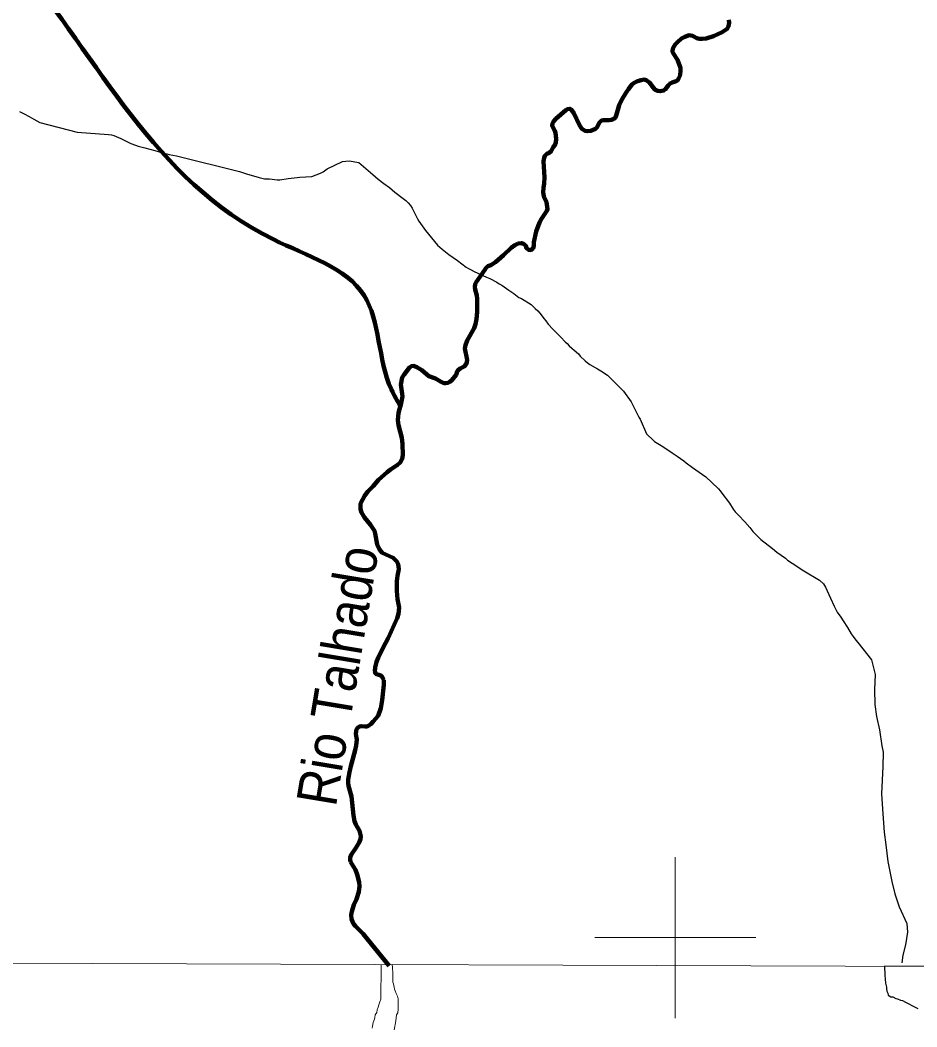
# Model space of a CAD drawing. Extents: x 553962 to 842807, y 8883888 to 9032388.
# Drawn here: x 616862 to 628002, y 8948891 to 8961392 of the extents above; entities that cross this region are included whole.
import ezdxf
from ezdxf.enums import TextEntityAlignment as Align

# ---------------------------------------------------------------- set-up
doc = ezdxf.new("R2010")
doc.units = 0
doc.header["$LTSCALE"] = 200
for name, color, linetype, lineweight in [('1', 7, 'Continuous', 13), ('12', 7, 'Continuous', 25), ('2', 7, 'Continuous', 13), ('21', 7, 'Continuous', 25), ('24', 7, 'Continuous', 25), ('25', 7, 'Continuous', 13), ('9', 7, 'Continuous', 90)]:
    doc.layers.add(name, color=color, linetype=linetype, lineweight=lineweight)
doc.layers.add('49', color=7, linetype='Continuous')

msp = doc.modelspace()

# ---------------------------------------------------------------- linework, layer by layer
at = {"layer": '1'}
msp.add_line((565315.3, 8949866.8), (791497.7, 8949052.2), dxfattribs=at)
at = {"layer": '12'}
for points in [[(616854.8, 8960258.8), (616911.9, 8960228.8), (616972.5, 8960193.8), (617033, 8960160.9), (617107.9, 8960123.1)], [(617107.9, 8960123.1), (617571.3, 8960000.1), (617961.2, 8959971.1), (617997, 8959967.1), (618026, 8959959.2), (618054, 8959949.2), (618114.7, 8959924.2), (618235.7, 8959862.3), (618293.7, 8959838.4), (618327.5, 8959827.4), (618413, 8959804.5), (618473.5, 8959791.6), (618533.2, 8959772.7), (618617.9, 8959748.8), (618652.5, 8959740.8), (618682.4, 8959731.8), (618711.4, 8959723.9), (618803.6, 8959709), (619586.3, 8959511.3)], [(619831.3, 8959436.2), (619865.1, 8959428.2), (619897.1, 8959423.3), (619929, 8959423.3), (619960.1, 8959421.4), (620056, 8959410.5), (620088, 8959410.6), (620193.3, 8959426.8), (620302, 8959438.9), (620338.3, 8959444), (620485.1, 8959452.2), (620592.3, 8959491.5), (620626.6, 8959508.6), (620677.1, 8959543.7), (620866.8, 8959636.1), (620950.1, 8959645.3), (621067.6, 8959622.4), (621213.8, 8959498.5), (621277.5, 8959446.5), (621310.7, 8959416.5), (621378.9, 8959364.5), (621451.2, 8959312.6), (621517.4, 8959257.6), (621620.6, 8959177.6), (621652, 8959151.6), (621681.1, 8959122.6), (621709.4, 8959090.6), (621730.8, 8959055.6), (621766, 8958989.6), (621797.6, 8958926.5), (621816.7, 8958894.5), (621897.9, 8958779.4), (622047.1, 8958598.4), (622104.4, 8958547.4), (622189, 8958482.4), (622295.2, 8958408.5), (622402.8, 8958323.5), (622432, 8958306.5), (622464.2, 8958290.6), (622503.3, 8958272.6), (622656.9, 8958198.7), (622695.9, 8958184.8), (622781.7, 8958137.8), (622814.5, 8958116.8), (622845, 8958100.9), (622933, 8958040.9), (622994, 8957997), (623055.6, 8957949), (623090.1, 8957935), (623208.6, 8957861.1), (623261.3, 8957811.1), (623293.1, 8957783.1), (623319, 8957753.1), (623370.1, 8957684.1), (623394.1, 8957657.1), (623423, 8957618), (623480.8, 8957556), (623503.5, 8957528), (623577.3, 8957455), (623634.3, 8957397), (623656.2, 8957377), (623681.5, 8957349), (623715.2, 8957318), (623746.4, 8957294), (623796.4, 8957250.1), (623820, 8957220), (623881.1, 8957162.1), (623907.7, 8957139.1), (623938.3, 8957116.1), (624032.6, 8957060.1), (624097.3, 8957025.2), (624126.4, 8957005.2), (624156.6, 8956982.2), (624209.6, 8956933.2), (624300.1, 8956843.2), (624356.6, 8956783.2), (624452.3, 8956653.2), (624547.5, 8956464), (624563.3, 8956437), (624643.8, 8956253.8), (624732.1, 8956169.8), (624741.4, 8956157.8), (624844.8, 8956096.9), (624963, 8956021), (625024.6, 8955976), (625106.9, 8955919.1), (625134.8, 8955896.1), (625215.8, 8955838.1), (625381.6, 8955722.2), (625453.3, 8955650.2), (625539.4, 8955570.2), (625559, 8955549.2), (625578.1, 8955517.2), (625672.3, 8955394.1), (625719.6, 8955321.1), (625744.1, 8955288.1), (625787.2, 8955246.1), (625865, 8955162.1), (625928.3, 8955090.1), (625962.8, 8955044), (626062.5, 8954941)], [(619586.3, 8959511.3), (619636.3, 8959496), (619674.1, 8959485), (619831.3, 8959436.2)], [(626062.5, 8954941), (626210.1, 8954830.1), (626263.6, 8954786.1), (626369.3, 8954710.2), (626395.7, 8954688.2), (626508.6, 8954610.2), (626539.2, 8954592.2), (626598.2, 8954554.3), (626792.1, 8954439.4), (626840.8, 8954390.4), (626864.8, 8954350.4), (626929.5, 8954214.3), (626976, 8954113.2), (627012.7, 8954042.1), (627056.3, 8953977.1), (627085.1, 8953931.1), (627140.4, 8953852), (627187.4, 8953773), (627209.8, 8953740), (627243.8, 8953694), (627268.1, 8953665), (627437.5, 8953449.9)], [(627437.5, 8953449.9), (627481.8, 8953267.7), (627474.2, 8953079.4), (627481, 8952894.1), (627502, 8952745.9), (627539.5, 8952577.7), (627565.1, 8952382.4), (627583.5, 8952301.3), (627578.9, 8952122), (627564.2, 8951783.5), (627578, 8951538.1), (627594.5, 8951309.8), (627615.6, 8951152.6), (627641.3, 8950944.3), (627690, 8950694), (627726.6, 8950540.8), (627780.8, 8950380.6), (627876.2, 8950172.5), (627886.3, 8950067.3), (627860.6, 8949911), (627825.7, 8949779.8), (627813.3, 8949686.6)]]:
    msp.add_lwpolyline(points, dxfattribs=at)
at = {"layer": '2'}
for p, q in [((625000, 8949000), (625000, 8951000)), ((624000, 8950000), (626000, 8950000))]:
    msp.add_line(p, q, dxfattribs=at)
at = {"layer": '21'}
msp.add_lwpolyline([(628960.2, 8949636.4), (627600.1, 8949642.9), (627603.7, 8949532.3), (627605.9, 8949482.3), (627610.5, 8949432.2), (627625.2, 8949384.6), (627625.1, 8949364.6), (627627.4, 8949332), (627639.7, 8949309.5), (627644.5, 8949284.4), (627676.9, 8949264.2), (627704.4, 8949261.6), (627739.3, 8949243.9), (627761.7, 8949238.7), (627796.6, 8949223.5), (627824.1, 8949218.4), (627859, 8949198.2), (627903.8, 8949177.9), (627948.7, 8949152.7), (628014.1, 8949120.8)], dxfattribs=at)
at = {"layer": '24'}
for points in [[(625664.5, 8961397.5), (625669.9, 8961359.4), (625663.1, 8961316.3), (625644, 8961283.3), (625582.5, 8961243.1), (625473.5, 8961191.8)], [(625473.5, 8961191.8), (625385.3, 8961162.7), (625335.4, 8961158.6), (625297, 8961160.5), (625268.2, 8961168.5), (625214.1, 8961198.5), (625173.4, 8961205.4), (625117.9, 8961186.3), (625078.9, 8961163.2), (625027.5, 8961119), (625000.9, 8961089), (624975.3, 8961048.8), (624966.1, 8961016.8), (624966.2, 8960999.8), (624973, 8960982.7), (625029.9, 8960900.7), (625064.6, 8960798.6), (625067, 8960768.6), (625061.1, 8960709.5), (625046, 8960671.4), (625027.5, 8960644.3), (625011.3, 8960634.2), (624961, 8960619.2), (624936.3, 8960606.1), (624912, 8960582), (624879.5, 8960536.9), (624854.3, 8960516.8), (624811.3, 8960509.7), (624784.5, 8960512.7), (624750.7, 8960527.7), (624725.6, 8960556.7), (624680, 8960618.7), (624640.1, 8960648.7), (624615.7, 8960653.7), (624577.3, 8960648.6), (624531.2, 8960635.5), (624496.8, 8960619.4)], [(624496.8, 8960619.4), (624466.5, 8960595.3), (624466.5, 8960595.3), (624418.2, 8960536.2), (624388.4, 8960493.1), (624334.1, 8960398.8), (624304.9, 8960334.7), (624271.6, 8960219.4), (624255.9, 8960184.4), (624237, 8960167.3), (624209.4, 8960152.2), (624177.8, 8960149.2), (624105.6, 8960150.1), (624084, 8960144), (624056.4, 8960117.9), (624029.7, 8960062.8), (624008.5, 8960040.7), (623952.6, 8960017.6), (623906.6, 8960011.5), (623879.7, 8960018.5), (623839.9, 8960041.5), (623809.1, 8960087.5), (623742.1, 8960236.6), (623708.6, 8960280.6), (623691, 8960291.6), (623663.5, 8960287.6), (623642.3, 8960274.5), (623518.1, 8960166.2), (623487.9, 8960132.1), (623473.9, 8960107), (623469.3, 8960080), (623503, 8960016.9), (623511.8, 8959991.9), (623518.8, 8959918.8), (623515.2, 8959871.7), (623503, 8959841.6), (623483.8, 8959814.6), (623458.3, 8959764.4), (623435.3, 8959743.4), (623405.8, 8959733.3), (623380.1, 8959708.2), (623370, 8959684.2), (623363, 8959639.1), (623374, 8959437.8), (623371.3, 8959365.7), (623362.7, 8959309.6), (623359.5, 8959254.5), (623367, 8959203.4), (623399.7, 8959131.4), (623414.8, 8959045.2), (623404.2, 8959022.2), (623338.3, 8958926.9), (623315, 8958880.8), (623272.9, 8958769.6), (623243.1, 8958633.3), (623241.6, 8958590.3), (623234, 8958561.2), (623207.1, 8958537.1), (623180.9, 8958538.1), (623154, 8958559.1), (623142.4, 8958588.1), (623129.2, 8958606.1), (623114.3, 8958616.1), (623091.3, 8958624.1), (623048.1, 8958618)], [(623048.1, 8958618), (623008.6, 8958598.9), (622961, 8958563.8), (622867, 8958474.5), (622765.3, 8958385.2), (622710.3, 8958350.1), (622672.6, 8958336), (622645.8, 8958310.9), (622635.8, 8958292.8), (622526.4, 8958139.4), (622516.5, 8958114.4), (622511.7, 8958078.3), (622515.3, 8958048.3), (622533.3, 8957971.2), (622537.7, 8957930.1), (622539.2, 8957771.9), (622532.6, 8957678.7), (622519.6, 8957617.6), (622503, 8957566.5), (622414.7, 8957413.1), (622392.8, 8957358), (622387.2, 8957313.9), (622413.1, 8957173.7), (622412, 8957144.7), (622401.3, 8957121.6), (622379.3, 8957091.6), (622329.5, 8957067.4), (622303.6, 8957046.4), (622292.3, 8957028.3), (622277.2, 8956988.2), (622224.7, 8956922.1), (622199.4, 8956902), (622173.6, 8956888.9), (622144.5, 8956882.9), (622124.1, 8956884.8), (622082.2, 8956903.8), (622023.4, 8956940.8)], [(622023.4, 8956940.8), (621940, 8956970.7), (621852.9, 8957044.7), (621852.9, 8957044.7), (621788.3, 8957084.6), (621747.1, 8957098.6), (621722, 8957094.5), (621699.9, 8957079.5), (621630.5, 8956993.2), (621609.1, 8956955.1), (621593, 8956869), (621597.7, 8956809.9), (621609.5, 8956752.8), (621610.3, 8956716.8), (621596.7, 8956635.6), (621564.2, 8956517.4), (621555.7, 8956425.2), (621563.4, 8956363.1), (621602.1, 8956205), (621612.3, 8956132.8), (621617.2, 8955989.6), (621609.4, 8955942.6), (621581.9, 8955900.4), (621546.5, 8955864.3), (621462.3, 8955810.1), (621421.6, 8955778), (621315.5, 8955681.7), (621248.5, 8955606.5), (621180.3, 8955539.2), (621144.2, 8955490.1), (621090.8, 8955387.9), (621089.6, 8955318.8), (621102.6, 8955276.7), (621141.2, 8955216.7), (621216.2, 8955123.7), (621263.9, 8955050.6), (621273.7, 8955018.6), (621298.4, 8954880.4), (621326.6, 8954818.3), (621344.8, 8954792.3), (621361.2, 8954778.3), (621494.9, 8954716.5), (621540.7, 8954668.5), (621556.5, 8954637.4), (621563.9, 8954607.4), (621564.5, 8954574.3), (621548.8, 8954491.2), (621540.9, 8954424.1), (621539.7, 8954301.9), (621548, 8954202.7), (621568.6, 8954096.6), (621562.7, 8954019.5), (621547, 8953964.4), (621433.8, 8953717.8), (621371.7, 8953602.5), (621309.6, 8953474.2), (621290.3, 8953424.1), (621271.3, 8953352), (621268.5, 8953307.9), (621278.3, 8953276.9), (621286.8, 8953268.9), (621318.5, 8953261.9), (621350.1, 8953247.9), (621369.2, 8953222.9), (621379.6, 8953197.9)], [(621379.6, 8953197.9), (621378.8, 8953137.8), (621359.7, 8952949.5), (621342.4, 8952846.3), (621307.8, 8952755.1), (621249.5, 8952681.9), (621219.1, 8952650.8), (621195, 8952631.7), (621171.1, 8952622.7), (621146.2, 8952620.6), (621100.1, 8952625.6), (621079.8, 8952621.5), (621057, 8952606.5), (621039.6, 8952581.4), (621035.3, 8952565.4), (621033.6, 8952527.3), (621045.1, 8952461.2), (621037.1, 8952383.1), (621025.7, 8952328), (620968.5, 8952127.6), (620952.3, 8952055.4), (620937.5, 8951961.3), (620936.1, 8951922.2), (620941.1, 8951883.2), (620980.3, 8951750), (621003, 8951516.7), (621017.4, 8951444.6), (621032.5, 8951402.6), (621077.7, 8951325.5), (621094.2, 8951257.4), (621089.4, 8951221.4), (621074.5, 8951180.3), (621038, 8951120.1), (620972.8, 8951028.9), (620962.2, 8950992.8), (620961.5, 8950967.8), (620966.3, 8950940.7)], [(620966.3, 8950940.7), (621026.2, 8950839.7), (621050.6, 8950784.6), (621074.2, 8950687.5), (621074.2, 8950687.5), (621078.6, 8950636.4), (621071, 8950569.3), (621042.3, 8950477.1), (621007.8, 8950405), (620980.8, 8950323.8), (620974.5, 8950282.7), (620979, 8950226.6), (621004.6, 8950171.6), (621028.3, 8950139.6), (621076, 8950091.6), (621124, 8950045.4), (621171.1, 8949985.9), (621444.2, 8949646.6)]]:
    msp.add_lwpolyline(points, dxfattribs=at)
at = {"layer": '25'}
for points in [[(621482.8, 8949664.5), (621346.7, 8949661.5), (621346.4, 8949629), (621346.2, 8949603.9), (621346.1, 8949583.9), (621345.8, 8949551.4), (621345.6, 8949523.8), (621345.4, 8949491.3), (621345.1, 8949458.7), (621342.3, 8949423.7), (621342, 8949383.7), (621341.8, 8949356.1), (621341.6, 8949328.6), (621341.3, 8949293.5), (621341.1, 8949261), (621340.9, 8949236), (621330.6, 8949201), (621317.8, 8949163.5), (621310.1, 8949133.5), (621297.4, 8949103.6), (621292.1, 8949071.1), (621271.9, 8949038.6), (621266.7, 8949008.6), (621264, 8948986.1), (621248.7, 8948946.2), (621240.8, 8948898.6), (621233.1, 8948876.2)], [(621508.1, 8948851.8), (621515.9, 8948894.3), (621521.1, 8948919.3), (621528.9, 8948964.3), (621534.2, 8949001.8), (621537, 8949041.9), (621552.2, 8949066.8), (621557.6, 8949109.3), (621557.8, 8949146.9), (621558.1, 8949184.5), (621558.3, 8949204.5), (621556, 8949237), (621551.3, 8949272.1), (621531.5, 8949304.8), (621519.3, 8949339.9), (621511.9, 8949360), (621509.6, 8949382.6), (621502.3, 8949405.1), (621499.9, 8949425.2), (621492.6, 8949447.8), (621490.3, 8949470.3), (621490.4, 8949490.3), (621490.6, 8949510.3), (621490.7, 8949530.4), (621490.9, 8949550.4), (621491, 8949572.9), (621488.8, 8949605.5), (621486.5, 8949638.1), (621484.2, 8949658.1), (621482.8, 8949664.5)]]:
    msp.add_lwpolyline(points, dxfattribs=at)
at = {"layer": '9'}
for points in [[(625664.5, 8961397.5), (625669.9, 8961359.4), (625663.1, 8961316.3), (625644, 8961283.3), (625582.5, 8961243.1), (625473.5, 8961191.8)], [(625473.5, 8961191.8), (625385.3, 8961162.7), (625335.4, 8961158.6), (625297, 8961160.5), (625268.2, 8961168.5), (625214.1, 8961198.5), (625173.4, 8961205.4), (625117.9, 8961186.3), (625078.9, 8961163.2), (625027.5, 8961119), (625000.9, 8961089), (624975.3, 8961048.8), (624966.1, 8961016.8), (624966.2, 8960999.8), (624973, 8960982.7), (625029.9, 8960900.7), (625064.6, 8960798.6), (625067, 8960768.6), (625061.1, 8960709.5), (625046, 8960671.4), (625027.5, 8960644.3), (625011.3, 8960634.2), (624961, 8960619.2), (624936.3, 8960606.1), (624912, 8960582), (624879.5, 8960536.9), (624854.3, 8960516.8), (624811.3, 8960509.7), (624784.5, 8960512.7), (624750.7, 8960527.7), (624725.6, 8960556.7), (624680, 8960618.7), (624640.1, 8960648.7), (624615.7, 8960653.7), (624577.3, 8960648.6), (624531.2, 8960635.5), (624496.8, 8960619.4)], [(624496.8, 8960619.4), (624466.5, 8960595.3), (624466.5, 8960595.3), (624418.2, 8960536.2), (624388.4, 8960493.1), (624334.1, 8960398.8), (624304.9, 8960334.7), (624271.6, 8960219.4), (624255.9, 8960184.4), (624237, 8960167.3), (624209.4, 8960152.2), (624177.8, 8960149.2), (624105.6, 8960150.1), (624084, 8960144), (624056.4, 8960117.9), (624029.7, 8960062.8), (624008.5, 8960040.7), (623952.6, 8960017.6), (623906.6, 8960011.5), (623879.7, 8960018.5), (623839.9, 8960041.5), (623809.1, 8960087.5), (623742.1, 8960236.6), (623708.6, 8960280.6), (623691, 8960291.6), (623663.5, 8960287.6), (623642.3, 8960274.5), (623518.1, 8960166.2), (623487.9, 8960132.1), (623473.9, 8960107), (623469.3, 8960080), (623503, 8960016.9), (623511.8, 8959991.9), (623518.8, 8959918.8), (623515.2, 8959871.7), (623503, 8959841.6), (623483.8, 8959814.6), (623458.3, 8959764.4), (623435.3, 8959743.4), (623405.8, 8959733.3), (623380.1, 8959708.2), (623370, 8959684.2), (623363, 8959639.1), (623374, 8959437.8), (623371.3, 8959365.7), (623362.7, 8959309.6), (623359.5, 8959254.5), (623367, 8959203.4), (623399.7, 8959131.4), (623414.8, 8959045.2), (623404.2, 8959022.2), (623338.3, 8958926.9), (623315, 8958880.8), (623272.9, 8958769.6), (623243.1, 8958633.3), (623241.6, 8958590.3), (623234, 8958561.2), (623207.1, 8958537.1), (623180.9, 8958538.1), (623154, 8958559.1), (623142.4, 8958588.1), (623129.2, 8958606.1), (623114.3, 8958616.1), (623091.3, 8958624.1), (623048.1, 8958618)], [(623048.1, 8958618), (623008.6, 8958598.9), (622961, 8958563.8), (622867, 8958474.5), (622765.3, 8958385.2), (622710.3, 8958350.1), (622672.6, 8958336), (622645.8, 8958310.9), (622635.8, 8958292.8), (622526.4, 8958139.4), (622516.5, 8958114.4), (622511.7, 8958078.3), (622515.3, 8958048.3), (622533.3, 8957971.2), (622537.7, 8957930.1), (622539.2, 8957771.9), (622532.6, 8957678.7), (622519.6, 8957617.6), (622503, 8957566.5), (622414.7, 8957413.1), (622392.8, 8957358), (622387.2, 8957313.9), (622413.1, 8957173.7), (622412, 8957144.7), (622401.3, 8957121.6), (622379.3, 8957091.6), (622329.5, 8957067.4), (622303.6, 8957046.4), (622292.3, 8957028.3), (622277.2, 8956988.2), (622224.7, 8956922.1), (622199.4, 8956902), (622173.6, 8956888.9), (622144.5, 8956882.9), (622124.1, 8956884.8), (622082.2, 8956903.8), (622023.4, 8956940.8)], [(622023.4, 8956940.8), (621940, 8956970.7), (621852.9, 8957044.7), (621852.9, 8957044.7), (621788.3, 8957084.6), (621747.1, 8957098.6), (621722, 8957094.5), (621699.9, 8957079.5), (621630.5, 8956993.2), (621609.1, 8956955.1), (621593, 8956869), (621597.7, 8956809.9), (621609.5, 8956752.8), (621610.3, 8956716.8), (621596.7, 8956635.6), (621564.2, 8956517.4), (621555.7, 8956425.2), (621563.4, 8956363.1), (621602.1, 8956205), (621612.3, 8956132.8), (621617.2, 8955989.6), (621609.4, 8955942.6), (621581.9, 8955900.4), (621546.5, 8955864.3), (621462.3, 8955810.1), (621421.6, 8955778), (621315.5, 8955681.7), (621248.5, 8955606.5), (621180.3, 8955539.2), (621144.2, 8955490.1), (621090.8, 8955387.9), (621089.6, 8955318.8), (621102.6, 8955276.7), (621141.2, 8955216.7), (621216.2, 8955123.7), (621263.9, 8955050.6), (621273.7, 8955018.6), (621298.4, 8954880.4), (621326.6, 8954818.3), (621344.8, 8954792.3), (621361.2, 8954778.3), (621494.9, 8954716.5), (621540.7, 8954668.5), (621556.5, 8954637.4), (621563.9, 8954607.4), (621564.5, 8954574.3), (621548.8, 8954491.2), (621540.9, 8954424.1), (621539.7, 8954301.9), (621548, 8954202.7), (621568.6, 8954096.6), (621562.7, 8954019.5), (621547, 8953964.4), (621433.8, 8953717.8), (621371.7, 8953602.5), (621309.6, 8953474.2), (621290.3, 8953424.1), (621271.3, 8953352), (621268.5, 8953307.9), (621278.3, 8953276.9), (621286.8, 8953268.9), (621318.5, 8953261.9), (621350.1, 8953247.9), (621369.2, 8953222.9), (621379.6, 8953197.9)], [(621379.6, 8953197.9), (621378.8, 8953137.8), (621359.7, 8952949.5), (621342.4, 8952846.3), (621307.8, 8952755.1), (621249.5, 8952681.9), (621219.1, 8952650.8), (621195, 8952631.7), (621171.1, 8952622.7), (621146.2, 8952620.6), (621100.1, 8952625.6), (621079.8, 8952621.5), (621057, 8952606.5), (621039.6, 8952581.4), (621035.3, 8952565.4), (621033.6, 8952527.3), (621045.1, 8952461.2), (621037.1, 8952383.1), (621025.7, 8952328), (620968.5, 8952127.6), (620952.3, 8952055.4), (620937.5, 8951961.3), (620936.1, 8951922.2), (620941.1, 8951883.2), (620980.3, 8951750), (621003, 8951516.7), (621017.4, 8951444.6), (621032.5, 8951402.6), (621077.7, 8951325.5), (621094.2, 8951257.4), (621089.4, 8951221.4), (621074.5, 8951180.3), (621038, 8951120.1), (620972.8, 8951028.9), (620962.2, 8950992.8), (620961.5, 8950967.8), (620966.3, 8950940.7)], [(620966.3, 8950940.7), (621026.2, 8950839.7), (621050.6, 8950784.6), (621074.2, 8950687.5), (621074.2, 8950687.5), (621078.6, 8950636.4), (621071, 8950569.3), (621042.3, 8950477.1), (621007.8, 8950405), (620980.8, 8950323.8), (620974.5, 8950282.7), (620979, 8950226.6), (621004.6, 8950171.6), (621028.3, 8950139.6), (621076, 8950091.6), (621124, 8950045.4), (621171.1, 8949985.9), (621444.2, 8949646.6)]]:
    msp.add_lwpolyline(points, dxfattribs=at)
msp.add_spline([(592698.5, 8977198.4), (599903.5, 8973292.7), (608459.2, 8968138.2), (612674.8, 8965332.6), (616842, 8962096.4), (620005, 8958671.2), (621134, 8957974.7), (621473.4, 8956805.3), (621586.2, 8956597.5)], degree=3, dxfattribs=at)

# ---------------------------------------------------------------- texts
at = {"layer": '49', "width": 0.9}
msp.add_text('Rio Talhado', height=500, rotation=80.538, dxfattribs=at).set_placement((621050.4, 8953212.3), align=Align.CENTER)

doc.saveas('drawing.dxf')
